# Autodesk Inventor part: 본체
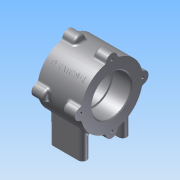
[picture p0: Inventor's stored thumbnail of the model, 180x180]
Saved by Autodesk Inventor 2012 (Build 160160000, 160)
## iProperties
Created: 2015-03
Part Number: 본체
Material: Default
Document SubType Name: Modeling
Designer: net
Density: 1 g/cm^3
Author: net
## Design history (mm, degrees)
sketch "스케치1"
  geometry: C1 r 37 at (0, 0); 1 further point
  constraints: 1 centre point, 1 coincident
  dimensions: "d0" = 74 diameter of C1
extrude "돌출1" new body sketch "스케치1" stored distance "d1" = 52; taper "d2" = 0 deg
sketch "스케치2"
  geometry: C1 r 7 at (0, 37); C2 r 7 at (-37, 0); C3 r 7 at (0, -37); C4 r 7 at (37, 0); A1 r 37 centre (0, 0) between (0, 37) and (-37, 0) reference
  constraints: 4 centre point, 4 point on circle, 2 horizontal alignment, 2 vertical alignment
  dimensions: "d3" = 14 diameter of C1; "d4" = 14 diameter of C2; "d5" = 14 diameter of C3; "d6" = 14 diameter of C4
extrude "돌출2" join sketch "스케치2" distance "d7" = 15; taper "d8" = 0 deg
sketch "스케치3"
  geometry: C1 r 7 at (0, 37); C2 r 7 at (37, 0); C3 r 7 at (0, -37); C4 r 7 at (-37, 0); A1 r 37 centre (0, 0) between (0, 37) and (37, 0) reference
  constraints: 4 centre point, 4 point on circle, 2 horizontal alignment, 2 vertical alignment
  dimensions: "d9" = 14 diameter of C1; "d10" = 14 diameter of C2; "d11" = 14 diameter of C3; "d12" = 14 diameter of C4
extrude "돌출3" join sketch "스케치3" distance "d13" = 15; taper "d14" = 0 deg
node "작업 평면1"
sketch "스케치4"
  geometry: L1 (0, 0)-(0, -58); L2 (0, -58)-(-24, -58); L3 (-24, -58)-(-29, -58); L4 (-29, -58)-(-19, -58); L5 (-19, -58)-(-19, -31.749); L6 (-29, -58)-(-29, -22.978); L7 (19, -58)-(19, -31.749); L8 (29, -58)-(29, -22.978); L9 (0, -58)-(24, -58); L10 (24, -58)-(29, -58); A1 r 37 centre (0, 0) between (-29, -22.978) and (-19, -31.749) reference; A2 r 37 centre (0, 0) between (19, -31.749) and (29, -22.978); A3 r 37 centre (0, 0) between (-29, -22.978) and (-19, -31.749); 1 further point
  constraints: 20 end point, 6 point on circle, 5 symmetric about line, 2 centre point, 2 perpendicular, 2 point on line, 1 coincident, 1 collinear, 1 parallel, 1 vertical
  dimensions: "d15" = 58 distance of L1.start L1.end; "d16" = 24 distance of L1.end L2.end; "d17" = 5 distance of L2.end L3.end; "d18" = 10 distance of L3.end L4.end
extrude "돌출4" join sketch "스케치4" stored distance "d20" = 40; taper "d21" = 0 deg
sketch "스케치5"
  geometry: C1 r 23.5 at (0, 0); A1 r 37 centre (0, 0) between (-6.969, 36.338) and (-36.338, 6.969) reference
  constraints: 1 centre point, 1 coincident
  dimensions: "d22" = 47 diameter of C1
extrude "돌출5" cut sketch "스케치5" distance "d23" = 22; taper "d24" = 0 deg
sketch "스케치6"
  geometry: C1 r 23.5 at (0, 0); A1 r 37 centre (0, 0) between (36.338, 6.969) and (6.969, 36.338) reference
  constraints: 1 centre point, 1 coincident
  dimensions: "d25" = 47 diameter of C1
extrude "돌출6" cut sketch "스케치6" distance "d26" = 22; taper "d27" = 0 deg
sketch "스케치7"
  geometry: C1 r 23.5 at (0, 0) reference; C2 r 21 at (0, 0)
  constraints: 1 centre point, 1 coincident
  dimensions: "d28" = 42 diameter of C2
extrude "돌출7" cut sketch "스케치7" distance "d29" = 22; taper "d30" = 0 deg
sketch "스케치8"
  geometry: A1 r 7 centre (0, 37) between (6.969, 36.338) and (-6.969, 36.338) reference; 1 further point
  constraints: 1 coincident
hole "구멍1" sketch "스케치8" at (0, 37) diameter "d31" = 3.242; stored, may be unused: countersink angle "d35" = 90 deg, drill point angle "d37" = 118 deg; dims "d32" = 8, "d33" = 4, "d34" = 2, "d36" = 11
sketch "스케치9"
  geometry: A1 r 7 centre (0, 37) between (6.969, 36.338) and (-6.969, 36.338) reference; 1 further point
  constraints: 1 coincident
hole "구멍2" sketch "스케치9" at (0, 37) diameter "d41" = 3.242; stored, may be unused: countersink angle "d45" = 90 deg, drill point angle "d47" = 118 deg; dims "d42" = 8, "d43" = 4, "d44" = 2, "d46" = 11
sketch "스케치10"
  geometry: L1 (0, 0)-(0, -40) reference; L2 (0, -40)-(10, -40) reference; L3 (-38, 0)-(-48, 0) reference; L4 (-48, -40)-(-48, 0) reference; L5 (-48, -40)-(-38, -40) reference; L6 (-38, 0)-(-38, -40) reference; L7 (5, -40)-(-43, -40); L8 (-43, -40)-(-43, -35); L9 (5, -40)-(5, -35); L10 (0, -20)-(-19, -20); 4 further points
  constraints: 8 end point, 3 midpoint, 2 coincident, 2 perpendicular, 2 symmetric about line, 1 parallel
  dimensions: "d51" = 48 distance of L7.start L7.end; "d52" = 5 distance of L7.end L8.end; "d53" = 5 distance of L7.start L9.end
hole "구멍3" sketch "스케치10" at (-43, -35), (5, -35), (-43, -5), (5, -5) diameter "d54" = 4.134; stored, may be unused: countersink angle "d58" = 90 deg, drill point angle "d60" = 118 deg; dims "d55" = 6, "d56" = 4, "d57" = 2, "d59" = 8
fillet "모깎기1" dims "d61" = 3
chamfer "모따기1" distance "d62" = 1; stored, may be unused: second distance "d63" = 2, angle "d64" = 45 deg
fillet "모깎기2" dims "d65" = 0.3
fillet "모깎기3" dims "d66" = 5
fillet "모깎기4" dims "d67" = 3
sketch "스케치11"
  geometry: L1 (-19, -36.661)-(-19, -58) reference; L2 (-19, -58)-(-29, -58) reference; L3 (-29, -58)-(-29, -24) reference; L4 (29, -24)-(29, -58) reference; L5 (29, -58)-(19, -58) reference; L6 (19, -58)-(19, -36.661) reference; L7 (0, 0)-(0, 12.332); L8 (0, 0)-(-26.163, 26.163); C1 r 21 at (0, 0) reference; A1 r 3 centre (16, -36.661) between (19, -36.661) and (14.8, -33.911) reference; A2 r 37 centre (0, 0) between (-14.8, -33.911) and (14.8, -33.911) reference; A3 r 3 centre (-16, -36.661) between (-14.8, -33.911) and (-19, -36.661) reference; A4 r 3 centre (-32, -24) between (-29, -24) and (-29.6, -22.2) reference; A5 r 37 centre (0, 0) between (29.6, -22.2) and (-29.6, -22.2) reference; A6 r 3 centre (32, -24) between (29.6, -22.2) and (29, -24) reference; 1 further point
  constraints: 4 end point, 1 parallel, 1 point on circle
  dimensions: "d68" = 45 deg angle of L8 L7
  node "절단 모서리 투영2"
node "작업 평면2"
sketch "스케치12"
  geometry: 2 further points
  constraints: 1 coincident, 1 other
feature "엠보싱1" sketch "스케치12" dims "d1" = 52, "d2" = 0, "d12" = 14, "d69" = 0.5, "d70" = 0
node "솔리드1"
pattern_circular "원형 패턴1" dims angle "d39" = 360 deg
pattern_circular "원형 패턴2" dims angle "d49" = 360 deg
node "투영된 루프1"
node "절단 모서리 투영1"
